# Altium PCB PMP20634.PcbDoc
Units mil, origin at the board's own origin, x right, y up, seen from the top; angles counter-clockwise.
Board outline 3525 x 1240 mil, 2 copper layers (Top Layer, Bottom Layer), stack 62 mil thick; 30 components, 22 nets, 73 pads, 19 vias.
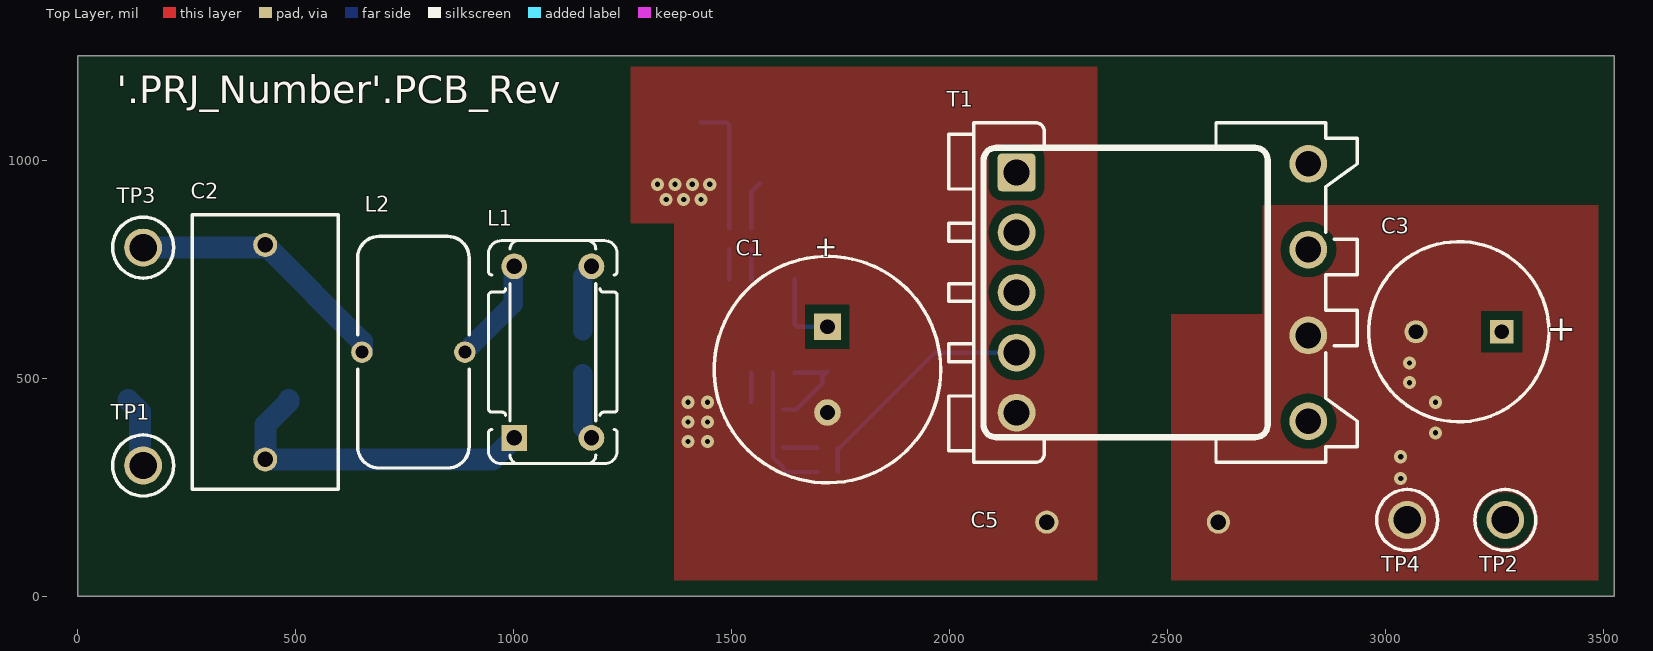
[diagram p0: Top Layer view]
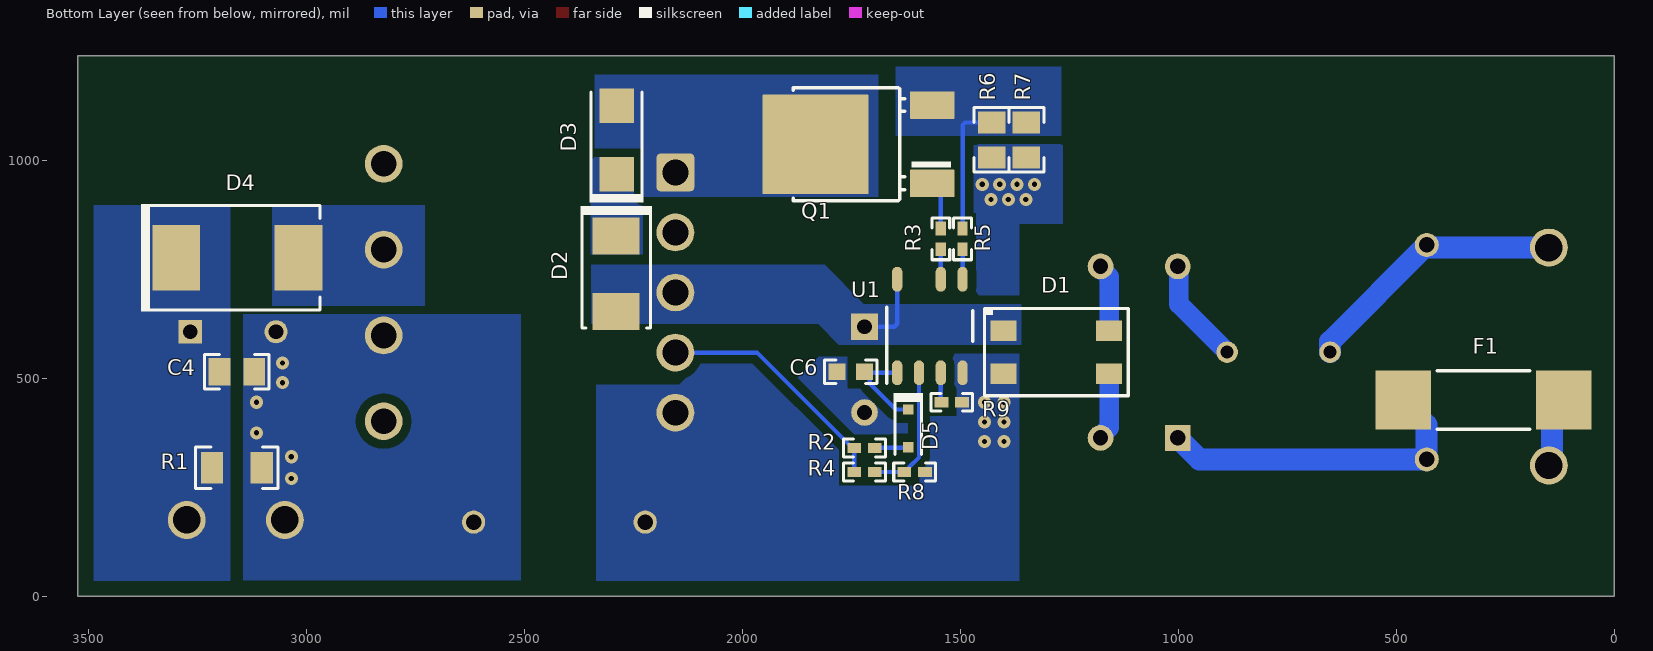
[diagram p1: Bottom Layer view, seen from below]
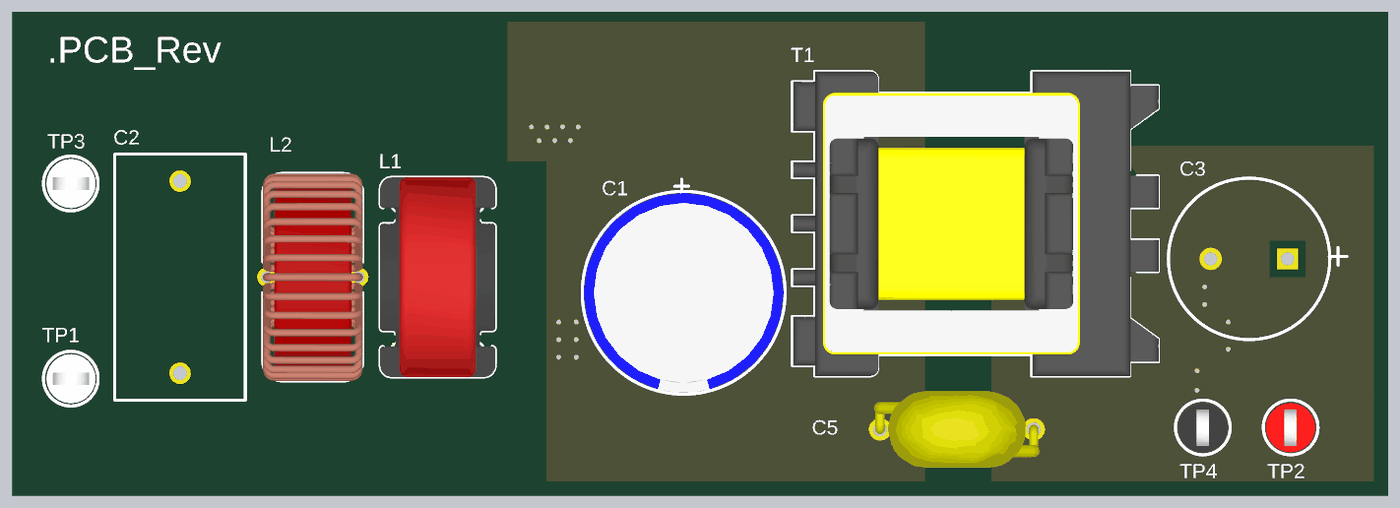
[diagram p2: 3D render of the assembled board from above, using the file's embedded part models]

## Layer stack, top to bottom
Top Solder: solder mask 0.4, Solder Resist, Dk 3.5
Top Layer: signal copper 1.4
Dielectric1: core 59.2, FR-4, Dk 4.8
Bottom Layer: signal copper 1.4
Bottom Solder: solder mask 0.4, Solder Resist, Dk 3.5

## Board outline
0,0 0,1240 3525,1240 3525,0

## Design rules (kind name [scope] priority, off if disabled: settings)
AcuteAngle [All] p1: minimum=4.50000000000000E+0001 checktracksonly=FALSE
AssemblyTestPointUsage [All] p1: valid=2
BoardOutlineClearance BoardOutlineClearance_MountingHoles [OnCopper and InComponentClass('Mounting Holes')] p1: gap=25 ignorepadtopadclearanceinfootprint=FALSE
BoardOutlineClearance BoardOutlineClearance_Poly [OnCopper and InPoly] p2: gap=25 ignorepadtopadclearanceinfootprint=FALSE
BoardOutlineClearance [OnCopper and Not InComponentClass('Logo') and not InComponentClass('FiducialMark') and not InRegion(1000,500,4000,800)] p3: gap=25 ignorepadtopadclearanceinfootprint=FALSE
Clearance Clearance_2 [InNetClass('HV') vs Not InNetClass('HV')] p1: gap=60 ignorepadtopadclearanceinfootprint=FALSE
Clearance Clearance_1 [InNetClass('MV') vs Not InNetClass('MV')] p2: gap=30 ignorepadtopadclearanceinfootprint=FALSE
Clearance Clearance_Keepouts [((IsTrack Or IsArc) And Not InPoly) And IsFree and IsKeepOut vs ((IsTrack Or IsArc) And Not InPoly) And IsFree and IsKeepOut] p3: gap=0 ignorepadtopadclearanceinfootprint=FALSE
Clearance Clearance_BoardEdge_MountingHoles [OnCopper and InComponentClass('Mounting Holes') vs IsKeepOut] p4: gap=40 ignorepadtopadclearanceinfootprint=FALSE except(0: Arc-Hole Track-Hole SMDPad-Hole THPad-Hole Via-Hole Fill-Hole Poly-Hole Region-Hole Text-Hole)
Clearance Clearance_BoardEdge_Poly [OnCopper and InPoly vs IsKeepOut] p5: gap=50 ignorepadtopadclearanceinfootprint=FALSE except(0: Arc-Hole Track-Hole SMDPad-Hole THPad-Hole Via-Hole Fill-Hole Poly-Hole Region-Hole Text-Hole)
Clearance Clearance_BoardEdge [OnCopper and Not InComponentClass('Logo') and not InComponentClass('FiducialMark') and not InRegion(1000,500,4000,800) and Not IsKeepout vs IsKeepOut] p6: gap=50 ignorepadtopadclearanceinfootprint=FALSE
Clearance Clearance_Poly [InPolygon] p7: gap=20 ignorepadtopadclearanceinfootprint=FALSE except(0: Arc-Hole Track-Hole SMDPad-Hole THPad-Hole Via-Hole Fill-Hole Poly-Hole Region-Hole Text-Hole)
Clearance [All] p8: gap=7.87 ignorepadtopadclearanceinfootprint=FALSE except(0: Arc-Hole Track-Hole SMDPad-Hole THPad-Hole Via-Hole Fill-Hole Poly-Hole Region-Hole Text-Hole)
ComponentClearance ComponentClearance_MountingHoles_FiducialMarks [InComponentClass('Mounting Holes') vs InComponentClass('FiducialMark')] p1: gap=20 collisioncheckmode=3 verticalgap=10 showdistances=FALSE
ComponentClearance ComponentClearance_Shunt [InComponentClass('Header') vs InComponentClass('Shunt')] p2: gap=0 collisioncheckmode=3 verticalgap=0 showdistances=FALSE
ComponentClearance ComponentClearance_Logo [InComponentClass('Logo')] p3: gap=5 collisioncheckmode=3 verticalgap=10 showdistances=FALSE
ComponentClearance ComponentClearance_ScrewToNut [(HasFootprint('NY PMS 440 0025 PH')) vs (HasFootprint('Keystone_1902C'))] p4: gap=20 collisioncheckmode=3 verticalgap=100000 showdistances=FALSE
ComponentClearance ComponentClearance_MountingHoles [InComponentClass('Mounting Holes')] p5: gap=20 collisioncheckmode=3 verticalgap=10 showdistances=FALSE
ComponentClearance ComponentClearance_SmallPassives [HasFootprint('0201*') or HasFootprint('0402*') or HasFootprint('0508') or HasFootprint('0603*') or HasFootprint('0612') or HasFootprint('0805*') or HasFootprint('0815*') or HasFootprint('0830*') or HasFootprint('1206*') or HasFootprint('1210*') or HasFootprint('1808*') or HasFootprint('1812*') or HasFootprint('1825*') or HasFootprint('2010*') or HasFootprint('2220*') or HasFootprint('2225*') or HasFootprint('2512*') or HasFootprint('2728*') or HasFootprint('3518*') vs HasFootprint('0201*') or HasFootprint('0402*') or HasFootprint('0508') or HasFootprint('0603*') or HasFootprint('0612') or HasFootprint('0805*') or HasFootprint('0815*') or HasFootprint('0830*') or HasFootprint('1206*') or HasFootprint('1210*') or HasFootprint('1808*') or HasFootprint('1812*') or HasFootprint('1825*') or HasFootprint('2010*') or HasFootprint('2220*') or HasFootprint('2225*') or HasFootprint('2512*') or HasFootprint('2728*') or HasFootprint('3518*')] p6: gap=20 collisioncheckmode=3 verticalgap=20 showdistances=FALSE
ComponentClearance ComponentClearance_THtoSMT [IsThruComponent vs IsSMTComponent] p7: gap=10 collisioncheckmode=3 verticalgap=10 showdistances=FALSE
ComponentClearance ComponentClearance_THtoTH [IsThruComponent vs IsThruComponent] p8: gap=10 collisioncheckmode=3 verticalgap=10 showdistances=FALSE
ComponentClearance [All] p9: gap=10 collisioncheckmode=3 verticalgap=10 showdistances=FALSE
DiffPairsRouting [All] p1: maxlimit=100 minlimit=10 mostfreqgap=10 toplayer_minwidth=15 toplayer_maxwidth=15 toplayer_prefwidth=15 bottomlayer_minwidth=15 bottomlayer_maxwidth=15 bottomlayer_prefwidth=15 maxuncoupledlength=1000
FabricationTestPointUsage TestPointUsage [All] p1: valid=2 allowmultiple=FALSE
FabricationTestpoint Testpoint [All] p1: side=3 testpointundercomponent=TRUE minsize=40 maxsize=100 preferedsize=60 minholesize=0 maxholesize=40 preferedholesize=32 testpointgrid=1 allowsidetop=TRUE allowsidebottom=TRUE usegrid=TRUE gridtolerance=0.01
FanoutControl Fanout_LCC [IsLCC] p1: bgadir=Out bgaviamode=Centered fanoutstyle=Auto fanoutdirection=Alternating viagrid=1 // Fanout_LCC (Default Rule)
FanoutControl Fanout_BGA [IsBGA] p2: bgadir=Out bgaviamode=Centered fanoutstyle=Auto fanoutdirection=Alternating viagrid=1 // Fanout_BGA (Default Rule)
FanoutControl Fanout_Default [All] p4: bgadir=Out bgaviamode=Centered fanoutstyle=Auto fanoutdirection=Alternating viagrid=1 // Fanout_Default (Default Rule)
FanoutControl Fanout_Small [(CompPinCount < 5)] p5: bgadir=Out bgaviamode=Centered fanoutstyle=Auto fanoutdirection=OutThenIn viagrid=1 // Fanout_Small (Default Rule)
Height [All] p1: minheight=0 maxheight=3000 prefheight=500
HoleSize [All] p1: absolutevalues=TRUE maxlimit=251 minlimit=7.87 maxpercent=80.000 minpercent=20.000
MinimumAnnularRing MinimumAnnularRing_ThermalPadVias [IsVia and InAnyComponent] p1: minimumring=5.91
MinimumAnnularRing [All] p2: minimumring=8
MinimumSolderMaskSliver MinimumSolderMaskSliver_Logo [InComponentClass('Logo') vs InComponentClass('Logo')] p1: minsoldermaskwidth=0.7
MinimumSolderMaskSliver [All] p2: minsoldermaskwidth=3.94
PlaneConnect [All] p1: planeconnectstyle=Direct reliefexpansion=10 reliefentries=4 reliefconductorwidth=10 reliefairgap=10
PolygonConnect PolygonConnect_15 [All vs IsNamedPolygon('C109_2') Or  IsNamedPolygon('C107_2') Or  IsNamedPolygon('HV') Or  IsNamedPolygon('Q203_5') Or  IsNamedPolygon('C107_2') Or  IsNamedPolygon('HS') Or  IsNamedPolygon('Q201_5') Or  IsNamedPolygon('Q203_5') Or  IsNamedPolygon('C106_2') Or  IsNamedPolygon('C108_2') Or  IsNamedPolygon('Vout') Or  IsNamedPolygon('Q203_5') Or  IsNamedPolygon('C108_2') Or  IsNamedPolygon('C113_2') Or  IsNamedPolygon('Q203_5') Or  IsNamedPolygon('Q201_5') Or  IsNamedPolygon('C107_2') Or  IsNamedPolygon('C102_1') Or  IsNamedPolygon('SGND') Or  IsNamedPolygon('GND') Or  IsNamedPolygon('SGND') Or  IsNamedPolygon('GND') Or  IsNamedPolygon('IN+') Or  IsNamedPolygon('IN+') Or  IsNamedPolygon('Q201_5') Or  IsNamedPolygon('Q201_5') Or  IsNamedPolygon('SGND') Or  IsNamedPolygon('SGND') Or  IsNamedPolygon('Vout') Or  IsNamedPolygon('Vout') Or  IsNamedPolygon('IN+') Or  IsNamedPolygon('GND') Or  IsNamedPolygon('IN+') Or  IsNamedPolygon('GND')] p1: connectstyle=Direct reliefconductorwidth=10 reliefentries=4 polygonreliefangle="90 Angle" airgapwidth=10
PolygonConnect PolygonConnect_14 [All vs IsNamedPolygon('C106_2') Or  IsNamedPolygon('C107_2') Or  IsNamedPolygon('C107_2') Or  IsNamedPolygon('C107_2') Or  IsNamedPolygon('C102_1') Or  IsNamedPolygon('Q203_5') Or  IsNamedPolygon('Vout') Or  IsNamedPolygon('Q203_5') Or  IsNamedPolygon('Q203_5') Or  IsNamedPolygon('Q201_5') Or  IsNamedPolygon('C108_2') Or  IsNamedPolygon('Q203_5') Or  IsNamedPolygon('HS') Or  IsNamedPolygon('HV') Or  IsNamedPolygon('C108_2') Or  IsNamedPolygon('Q201_5') Or  IsNamedPolygon('C109_2') Or  IsNamedPolygon('Q201_5') Or  IsNamedPolygon('Q201_5') Or  IsNamedPolygon('C113_2')] p2: connectstyle=Direct reliefconductorwidth=10 reliefentries=4 polygonreliefangle="90 Angle" airgapwidth=10
PolygonConnect PolygonConnect_13 [All vs IsNamedPolygon('C102_1') Or  IsNamedPolygon('HV') Or  IsNamedPolygon('C107_2') Or  IsNamedPolygon('C109_2') Or  IsNamedPolygon('C107_2') Or  IsNamedPolygon('C108_2') Or  IsNamedPolygon('C106_2') Or  IsNamedPolygon('C108_2') Or  IsNamedPolygon('C113_2') Or  IsNamedPolygon('C107_2')] p3: connectstyle=Direct reliefconductorwidth=10 reliefentries=4 polygonreliefangle="90 Angle" airgapwidth=10
PolygonConnect PolygonConnect_12 [All vs IsNamedPolygon('C107_2') Or  IsNamedPolygon('C113_2') Or  IsNamedPolygon('C106_2') Or  IsNamedPolygon('C107_2') Or  IsNamedPolygon('C107_2') Or  IsNamedPolygon('C102_1')] p4: connectstyle=Direct reliefconductorwidth=10 reliefentries=4 polygonreliefangle="90 Angle" airgapwidth=10
PolygonConnect PolygonConnect_11 [All vs IsNamedPolygon('C106_2') Or  IsNamedPolygon('C102_1') Or  IsNamedPolygon('C107_2') Or  IsNamedPolygon('C107_2') Or  IsNamedPolygon('C107_2')] p5: connectstyle=Direct reliefconductorwidth=10 reliefentries=4 polygonreliefangle="90 Angle" airgapwidth=10
PolygonConnect PolygonConnect_10 [All vs IsNamedPolygon('C106_2')] p6: connectstyle=Direct reliefconductorwidth=10 reliefentries=4 polygonreliefangle="90 Angle" airgapwidth=10
PolygonConnect PolygonConnect_9 [All vs IsNamedPolygon('C11_1') Or  IsNamedPolygon('Vin') Or  IsNamedPolygon('Vin') Or  IsNamedPolygon('5V') Or  IsNamedPolygon('D6_2') Or  IsNamedPolygon('Q3_3') Or  IsNamedPolygon('GND2') Or  IsNamedPolygon('GND2') Or  IsNamedPolygon('GND') Or  IsNamedPolygon('Q3_4') Or  IsNamedPolygon('12V5') Or  IsNamedPolygon('GND') Or  IsNamedPolygon('12V5') Or  IsNamedPolygon('D3_1')] p7: connectstyle=Direct reliefconductorwidth=10 reliefentries=4 polygonreliefangle="90 Angle" airgapwidth=10
PolygonConnect PolygonConnect_8 [All vs IsNamedPolygon('C11_1') Or  IsNamedPolygon('Vin') Or  IsNamedPolygon('12V5') Or  IsNamedPolygon('Q3_3') Or  IsNamedPolygon('GND2') Or  IsNamedPolygon('GND2') Or  IsNamedPolygon('5V') Or  IsNamedPolygon('Q3_4') Or  IsNamedPolygon('12V5')] p8: connectstyle=Direct reliefconductorwidth=10 reliefentries=4 polygonreliefangle="90 Angle" airgapwidth=10
PolygonConnect PolygonConnect_7 [All vs IsNamedPolygon('GND2') Or  IsNamedPolygon('GND2') Or  IsNamedPolygon('5V') Or  IsNamedPolygon('12V5') Or  IsNamedPolygon('12V5') Or  IsNamedPolygon('C11_1')] p9: connectstyle=Direct reliefconductorwidth=10 reliefentries=4 polygonreliefangle="90 Angle" airgapwidth=10
PolygonConnect PolygonConnect_6 [All vs IsNamedPolygon('GND2') Or  IsNamedPolygon('SGND') Or  IsNamedPolygon('GND1') Or  IsNamedPolygon('C901_1') Or  IsNamedPolygon('SGND') Or  IsNamedPolygon('GND2') Or  IsNamedPolygon('GND1')] p10: connectstyle=Direct reliefconductorwidth=10 reliefentries=4 polygonreliefangle="90 Angle" airgapwidth=10
PolygonConnect PolygonConnect_5 [All vs IsNamedPolygon('GND1') Or  IsNamedPolygon('GND1')] p11: connectstyle=Direct reliefconductorwidth=10 reliefentries=4 polygonreliefangle="90 Angle" airgapwidth=10
PolygonConnect PolygonConnect_4 [All vs IsNamedPolygon('C21_1') Or  IsNamedPolygon('C5_1') Or  IsNamedPolygon('C12_2') Or  IsNamedPolygon('C2_2') Or  IsNamedPolygon('C13_1') Or  IsNamedPolygon('C28_1') Or  IsNamedPolygon('C6_1') Or  IsNamedPolygon('GND') Or  IsNamedPolygon('GND2') Or  IsNamedPolygon('C14_1') Or  IsNamedPolygon('C13_1') Or  IsNamedPolygon('Q1_3') Or  IsNamedPolygon('C14_1') Or  IsNamedPolygon('C5_1') Or  IsNamedPolygon('GND2') Or  IsNamedPolygon('C28_1') Or  IsNamedPolygon('D5_2') Or  IsNamedPolygon('D6_2') Or  IsNamedPolygon('D2_1') Or  IsNamedPolygon('C12_2') Or  IsNamedPolygon('D2_1') Or  IsNamedPolygon('C4_1') Or  IsNamedPolygon('C4_1') Or  IsNamedPolygon('C2_2') Or  IsNamedPolygon('GND') Or  IsNamedPolygon('C33_1') Or  IsNamedPolygon('C9_1')] p12: connectstyle=Direct reliefconductorwidth=10 reliefentries=4 polygonreliefangle="90 Angle" airgapwidth=10
PolygonConnect PolygonConnect_3 [All vs IsNamedPolygon('C28_1') Or  IsNamedPolygon('C12_2') Or  IsNamedPolygon('C28_1') Or  IsNamedPolygon('C9_1') Or  IsNamedPolygon('D5_2') Or  IsNamedPolygon('C12_2') Or  IsNamedPolygon('C2_2') Or  IsNamedPolygon('C14_1') Or  IsNamedPolygon('C4_1') Or  IsNamedPolygon('C14_1') Or  IsNamedPolygon('D6_2') Or  IsNamedPolygon('GND2') Or  IsNamedPolygon('Q1_3') Or  IsNamedPolygon('C5_1') Or  IsNamedPolygon('D2_1') Or  IsNamedPolygon('C4_1') Or  IsNamedPolygon('C13_1') Or  IsNamedPolygon('C5_1') Or  IsNamedPolygon('C13_1') Or  IsNamedPolygon('C33_1') Or  IsNamedPolygon('D2_1') Or  IsNamedPolygon('GND') Or  IsNamedPolygon('GND') Or  IsNamedPolygon('GND2') Or  IsNamedPolygon('C2_2') Or  IsNamedPolygon('C6_1') Or  IsNamedPolygon('C21_1')] p13: connectstyle=Direct reliefconductorwidth=10 reliefentries=4 polygonreliefangle="90 Angle" airgapwidth=10
PolygonConnect PolygonConnect_2 [All vs IsNamedPolygon('C21_1') Or  IsNamedPolygon('C4_1') Or  IsNamedPolygon('D5_2') Or  IsNamedPolygon('C5_1') Or  IsNamedPolygon('C14_1') Or  IsNamedPolygon('C13_1') Or  IsNamedPolygon('C4_1') Or  IsNamedPolygon('C33_1') Or  IsNamedPolygon('C12_2') Or  IsNamedPolygon('D2_1') Or  IsNamedPolygon('C2_2') Or  IsNamedPolygon('C28_1') Or  IsNamedPolygon('C12_2') Or  IsNamedPolygon('D2_1') Or  IsNamedPolygon('C5_1') Or  IsNamedPolygon('Q1_3') Or  IsNamedPolygon('GND') Or  IsNamedPolygon('D6_2') Or  IsNamedPolygon('C6_1') Or  IsNamedPolygon('C2_2') Or  IsNamedPolygon('C14_1') Or  IsNamedPolygon('C28_1') Or  IsNamedPolygon('C13_1') Or  IsNamedPolygon('C9_1') Or  IsNamedPolygon('GND')] p14: connectstyle=Direct reliefconductorwidth=10 reliefentries=4 polygonreliefangle="90 Angle" airgapwidth=10
PolygonConnect PolygonConnect_1 [All vs IsNamedPolygon('C28_1') Or  IsNamedPolygon('D5_2') Or  IsNamedPolygon('C5_1') Or  IsNamedPolygon('C5_1') Or  IsNamedPolygon('D2_1') Or  IsNamedPolygon('C21_1') Or  IsNamedPolygon('C9_1') Or  IsNamedPolygon('C4_1') Or  IsNamedPolygon('C14_1') Or  IsNamedPolygon('C28_1') Or  IsNamedPolygon('C6_1') Or  IsNamedPolygon('C12_2') Or  IsNamedPolygon('C33_1') Or  IsNamedPolygon('C4_1') Or  IsNamedPolygon('C13_1') Or  IsNamedPolygon('C12_2') Or  IsNamedPolygon('D6_2') Or  IsNamedPolygon('C2_2') Or  IsNamedPolygon('C14_1') Or  IsNamedPolygon('D2_1') Or  IsNamedPolygon('C2_2') Or  IsNamedPolygon('C13_1')] p15: connectstyle=Direct reliefconductorwidth=10 reliefentries=4 polygonreliefangle="90 Angle" airgapwidth=10
PolygonConnect [All] p16: connectstyle=Direct reliefconductorwidth=10 reliefentries=4 polygonreliefangle="90 Angle" airgapwidth=10
RoutingVias ThermalPadVias [IsVia and InAnyComponent] p1: holewidth=7.87 width=19.68 viastyle="Through Hole" minholewidth=7.87 minwidth=19.68 maxholewidth=12.99 maxwidth=23.62
RoutingVias [All] p2: holewidth=16 width=34 viastyle="Through Hole" minholewidth=7.87 minwidth=20 maxholewidth=40 maxwidth=65
SilkToBoardRegionClearance [Not ((IsComment or IsDesignator) And (Hide <> 'False')) and not InRegion(1000,500,4000,800)] p1:
SilkToSilkClearance SilkToSilkClearance_Pb-FreeLogo [(HasFootprint('Pb-Free_Overlay_Medium') OR HasFootprint('Pb-Free_Overlay_Small')) vs (HasFootprint('Pb-Free_Overlay_Medium') OR HasFootprint('Pb-Free_Overlay_Small'))] p1: silktosilkclearance=0
SilkToSilkClearance [All] p2: silktosilkclearance=4
SilkToSolderMaskClearance SilkToComponentPadClearance [IsPad and InAnycomponent] p1: minsilkscreentomaskgap=5 clearancetoexposedcopper=TRUE
SilkToSolderMaskClearance "Silk to Solder Mask Opening" [All] p2: minsilkscreentomaskgap=4 clearancetoexposedcopper=FALSE
SolderMaskExpansion [All] p1: expansion=1.97 istentingtop=FALSE
Width [All] p1: maxlimit=100 minlimit=6 preferedwidth=10 checkconnectedcopper=TRUE
14 further rules are at their usual default settings.

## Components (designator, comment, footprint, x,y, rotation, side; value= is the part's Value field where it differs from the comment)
C1 "EKXG401ELL220MK20S" KXG_1250x2000 1720,520 r270 top value=22uF
C2 "ECQ-U3A104MG" ECQUG_1500x800x1500 430,560 r90 top value=0.1uF
C3 "EKZE250ELL681MJ20S" Chemi-Con_1000x2000 3168.58,606.85 r180 top value=680uF
C4 "GRM219R61E106KA12" 0805_HV 3160,515 r180 bottom value=10uF
C5 "VY1102M35Y5UQ63V0" VY1_900x500x1300 2420,170 r180 top value=1000pF
C6 "GRM188R6YA475KE15D" 0603 1751.5,515 r0 bottom value=4.7uF
D1 "RH06-T" MiniDIP 1280,560 r180 bottom value=600V
D2 "SMBJ150A-13-F" SMB 2290,740 r270 bottom value=150V
D3 "MURA160T3G" SMA 2288.58,1046.85 r90 bottom value=1.05V
D4 "B3100-13-F" SMC 3158.58,776.85 r180 bottom value=100V
D5 "BAS16J,135" SOD-323F 1620,385 r270 bottom value=100V
F1 "0443001.DR" FUSE_0443 300,450 r180 bottom
L1 "744821150" WE-CMB_XS 1090,560 r90 top value=5mH
L2 "7447031" WE-FI_1350x700 770,560 r0 top value=140uH
Q1 "FCD4N60TM" DPAK 1698.58,1036.85 r0 bottom value=600V
R1 "CRCW120610K0JNEA" 1206 3160,295 r0 bottom value=10k
R2 "CRCW04020000Z0ED" 0402 1720,340 r0 bottom value=0
R3 "CRCW04020000Z0ED" 0402 1545,820 r90 bottom value=0
R4 "CRCW040273K2FKED" 0402 1720,285 r0 bottom value=73.2k
R5 "CRCW04021K33FKED" 0402 1495,820 r90 bottom value=1.33k
R6 "CRCW08051R60JNEA" 0805_HV 1428.58,1046.85 r90 bottom value=1.6
R7 "CRCW08051R60JNEA" 0805_HV 1348.58,1046.85 r90 bottom value=1.6
R8 "CRCW040233K2FKED" 0402 1605,285 r0 bottom value=33.2k
R9 "CRCW0402115KFKED" 0402 1520,445 r0 bottom value=115k
T1 "750316686" Wurth_EE16-8-5_5280 2488.58,696.85 r0 top value=500uH
TP1 "5012" Keystone5012 150,300 r90 top
TP2 "5010" Keystone5010 3275,175 r0 top
TP3 "5012" Keystone5012 150,800 r90 top
TP4 "5011" Keystone5011 3050,175 r0 top
U1 "UCC28730DR" D0007A_N 1570,620 r90 bottom

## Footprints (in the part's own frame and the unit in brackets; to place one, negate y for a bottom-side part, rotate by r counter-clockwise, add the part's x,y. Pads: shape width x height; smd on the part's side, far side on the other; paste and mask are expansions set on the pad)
0402 [mm] "0402 from SM-752 data"
  rect 0.8x0.6 smd: 1(-0.6,0) 2(0.6,0)
  silkscreen extent -1.22,-0.52 1.22,0.52, body extent -0.55,-0.3 0.55,0.3, height 0.6
0603 [mm] "0603 from SM-752 data"
  rect 1x0.95 smd: 1(-0.8,0) 2(0.8,0)
  silkscreen extent -1.52,-0.69 1.52,0.69, body extent -0.87,-0.47 0.87,0.47, height 1
0805_HV [mil] "0805 with 30mil clearance between pads"
  rect 50x63 smd: 1(-40,0) 2(40,0)
  silkscreen extent -74,-40 74,40, body extent -43,-29 43,29, height 57
1206 [mm] "1206 from SM-752 data"
  rect 1.3x1.85 smd: 1(-1.45,0) 2(1.45,0)
  silkscreen extent -2.4,-1.21 2.4,1.21, body extent -1.7,-0.9 1.7,0.9, height 1.35
Chemi-Con_1000x2000 [mm] "TH, 2-Leads, Body 10x20mm, Pin Spacing 5mm"
  rect 1.35x1.35 hole 0.85: 1(-2.5,0)
  round 1.35 hole 0.85: 2(2.5,0)
  silkscreen extent -5.25,-5.25 5.25,5.25, body extent -5.25,-5.25 5.25,5.25, height 21.5
D0007A_N [mm] "SOIC, 7-Leads, Body 4.9x3.9mm, Pitch 1.27mm, IPC Medium Density"
  oval 1.45x0.6 smd: 1(-2.725,1.905) 2(-2.725,0.635) 3(-2.725,-0.635) 4(-2.725,-1.905) 5(2.725,-1.905) 6(2.725,-0.635) 8(2.725,1.905)
  silkscreen extent -3.32,-2.5 1.1,2.52, body extent -3.01,-2.45 3.01,2.45, height 1.75
DPAK [mm] "D-PAK, 3-Pads, Body 6.22x6.73mm (max), TO-252AA using nominal STEP model"
  rrect6% 2.6x1.6 smd: 1(-3.4,2.28) 3(-3.4,-2.28)
  rrect2% 6.2x5.8 smd paste-2.9: 4(3.4,0)
  silkscreen extent -4.5,-3.3 4.7,3.28, body extent -3.86,-3.29 5.84,3.29, height 2.48
ECQUG_1500x800x1500 [mm] "TH, 2-Leads, Body 15x8mm, Pin Spacing 12.5mm"
  round 1.4 hole 0.9: 1(-6.25,0) 2(6.25,0)
  silkscreen extent -8,-4.25 8,4.25, body extent -8,-4.25 8,4.25, height 15.5
FUSE_0443 [mm] "LITTELFUSE"
  rect 3.25x3.43 smd: 1(-4.675,0) 2(4.675,0)
  silkscreen extent -2.7,-1.7 2.7,1.7, body extent -5.05,-1.56 5.05,1.56, height 3.12
Keystone5010 [mil] "Keystone Multipurpose loops"
  round 87 hole 63: 1(0,0)
  silkscreen extent -70,-70 70,70, body extent -63,-63 63,62, height 319
Keystone5011 [mil] "Keystone Multipurpose loops"
  round 87 hole 63: 1(0,0)
  silkscreen extent -70,-70 70,70, body extent -63,-63 63,62, height 319
Keystone5012 [mil] "Keystone Multipurpose loops"
  round 87 hole 63: 1(0,0)
  silkscreen extent -70,-70 70,70, body extent -63,-63 63,62, height 319
KXG_1250x2000 [mm] "United Chemicon"
  rect 1.55x1.55 hole 0.85: 1(-2.5,0)
  round 1.55 hole 0.85: 2(2.5,0)
  silkscreen extent -6.6,-6.6 6.6,6.6, body extent -6.45,-6.49 6.49,6.49, height 21.51
MiniDIP [mm] "Land pattern created based on STEP model."
  rect 1.52x1.2 smd: 1(-3.075,1.25) 2(-3.075,-1.25) 3(3.075,-1.25) 4(3.075,1.25)
  silkscreen extent -4.19,-2.54 4.19,2.54, body extent -3.5,-2.45 3.5,2.45, height 2.75
SMA [mm] "Molded Diode, 2-Leads, Body 4.3x2.6mm, IPC Medium Density, based on OnSemi component dimensions and land pattern"
  rect 2x2 smd: 1(-2,0) 2(2,0)
  silkscreen extent -3.66,-1.57 2.79,1.57, body extent -2.6,-1.3 2.6,1.3, height 2.42
SMB [mil] "Molded Diode, 2-Leads, Body 5.4x3.6mm, IPC Medium Density, based on OnSemi component dimensions"
  rect 85x107.99 smd: 1(-87.01,0) 2(87.01,0)
  silkscreen extent -155,-82 125,82, body extent -106,-71 106,71, height 91
SMC [mil] "Molded Diode, 2-Leads, Body 6.9x5.8mm, IPC Medium Density, based on OnSemi component dimensions and land patterns"
  rect 110x150 smd: 1(-140.49,0) 2(140.49,0)
  silkscreen extent -221,-123 189,124, body extent -156,-116 157,116, height 91
SOD-323F [mm] "NXP recommended land pattern"
  rect 0.6x0.6 smd paste-0.05: 1(-1.1,0) 2(1.1,0)
  silkscreen extent -2.06,-0.86 1.53,0.86, body extent -1.35,-0.68 1.35,0.67, height 0.79
VY1_900x500x1300 [mm] "TH, Body 9x5mm, PinSpacing 10mm"
  round 1.35 hole 0.9: 1(-5,0) 2(5,0)
  body extent -5.4,-2.5 5.4,2.5, height 12.93
WE-CMB_XS [mm] "WE-CMB Series Size XS"
  rect 1.5x1.5 hole 0.9: 1(-5,2.25)
  round 1.5 hole 0.9: 2(-5,-2.25) 3(5,-2.25) 4(5,2.25)
  silkscreen extent -6.5,-3.75 6.5,3.75, body extent -6.5,-3.75 6.5,3.75, height 16.24
WE-FI_1350x700 [mm] "TH, 2-Leads, Dia 13.5mm"
  round 1.25 hole 0.75: 1(-3,0) 2(3,0)
  silkscreen extent -3.25,-6.75 3.25,6.75, body extent -3.25,-6.75 3.25,6.75, height 13.32
Wurth_EE16-8-5_5280 [mm] "Wurth"
  rrect20% 2.2x2.2 hole 1.5: 1(-8.5,7)
  round 2.2 hole 1.5: 2(-8.5,3.5) 3(-8.5,0) 4(-8.5,-3.5) 5(-8.5,-7) 6(8.5,-7.5) 7(8.5,-2.5) 8(8.5,2.5) 9(8.5,7.5)
  silkscreen extent -12.45,-9.9 11.36,9.9, body extent -12.4,-9.9 11.41,9.9, height 14.9

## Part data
C1: "CAP, AL, 22 µF, 400 V, +/- 20%, TH", Cap_Case=12.5x20, Manufacturer=Chemi-Con, Supplier Part Number 1=565-1463-ND, Tolerance_%=20, Value1=Unknown, Value2=400V, ValueDisplayed=22µF
C2: library part CMP-0012502-3, "CAP, Film, 0.1 uF, 300 V, +/- 20%, TH", Cap_Case=15x8x15mm, Manufacturer=Panasonic, Supplier Part Number 1=P11116-ND, Tolerance_%=20%, Value1=Unknown, Value2=300V, ValueDisplayed=0.1uF
C3: "CAP, AL, 680 µF, 25 V, +/- 20%, TH", Cap_Case=10x20, Manufacturer=Chemi-Con, Supplier Part Number 1=565-1679-ND, Tolerance_%=20, Value1=Unknown, Value2=25V, ValueDisplayed=680µF
C4: "CAP, CERM, 10 µF, 25 V, +/- 10%, X5R, 0805", Cap_Case=0805, Manufacturer=MuRata, Supplier Part Number 1=490-7207-1-ND, TempCo=X5R, Tolerance_%=10, Value1=Unknown, Value2=25V, ValueDisplayed=10µF
C5: library part CMP-0086097-1, "CAP, CERM, 1000 pF, X1 760 VAC/Y1 500 VAC, +/- 20%, Y5U, 9x5mm", Cap_Case=9X5mm, Manufacturer=Vishay-Bccomponents, TempCo=Y5U, Tolerance_%=20%, ValueDisplayed=1000pF
C6: "CAP, CERM, 4.7 µF, 35 V, +/- 10%, X5R, 0603", Cap_Case=0603, Manufacturer=MuRata, Supplier Part Number 1=490-7205-1-ND, TempCo=X5R, Tolerance_%=10, Value1=Unknown, Value2=35V, ValueDisplayed=4.7µF
D1: "Diode, Switching-Bridge, 600 V, 0.5 A, MiniDIP", Manufacturer="Diodes Inc.", Supplier Part Number 1=RH06DICT-ND, Value1=0.5A, Value2=1.15V
D2: "Diode, TVS, Uni, 150 V, 243 Vc, SMB", Manufacturer="Diodes Inc.", Power_W=5, Supplier Part Number 1=SMBJ150A-FDICT-ND, Value1=5W
D3: "Diode, Ultrafast, 600V, 1A, SMA", Manufacturer="ON Semiconductor", Supplier Part Number 1=MURA160T3GOSCT-ND, Value1=1A, Value2=600V
D4: "Diode, Schottky, 100 V, 3 A, SMC", Manufacturer="Diodes Inc.", Supplier Part Number 1=B3100-FDICT-ND, Value1=3A, Value2=0.79V
D5: "Diode, Switching, 100 V, 0.25 A, SOD-323F", Manufacturer="NXP Semiconductor", Supplier Part Number 1=568-5996-1-ND, Value1=0.25A, Value2=V
F1: "Fuse, 1 A, 250VAC/VDC, SMD", Irating_A=1, Manufacturer=Littelfuse, Supplier Part Number 1=F2906CT-ND
L1: library part CMP-0084275-1, "Coupled inductor, 5 mH, 0.22 ohm, TH", Manufacturer="Wurth Elektronik", ValueDisplayed=5mH
L2: library part CMP-0064732-2, "Inductor, Toroid, Powdered Iron, 140 uH, 1 A, 0.11 ohm, TH", Manufacturer="Wurth Elektronik", Value1="0.11 ohm", Value2=1A, ValueDisplayed=140uH
Q1: "MOSFET, N-CH, 600 V, 3.9 A, DPAK", Alternate Manufacturer=None, Manufacturer="Fairchild Semiconductor", Supplier Part Number 1=FCD4N60TMCT-ND, Value1="? ohm", Value2="12.8 nC"
R1: library part CMP-0018576-3, "RES, 10 k, 5%, 0.25 W, AEC-Q200 Grade 0, 1206", Manufacturer=Vishay-Dale, Power_W=250mW, Supplier Part Number 1=541-10KECT-ND, TempCo="200 ppm/C", Tolerance_%=5%, Value2=0.25W, Value_Code=10k0, ValueDisplayed=10k
R2 R3: "RES, 0, 5%, 0.063 W, 0402", Manufacturer=Vishay-Dale, Power_W=0.063, Supplier Part Number 1=541-0.0JCT-ND, TempCo="200 ppm/C", Tolerance_%=5, Value1=5%, Value2=0.063W, Value_Code=0000, ValueDisplayed=0
R4: "RES, 73.2 k, 1%, 0.063 W, 0402", Manufacturer=Vishay-Dale, Power_W=0.063, Supplier Part Number 1=541-73.2KLCT-ND, TempCo="100 ppm/C", Tolerance_%=1, Value1=1%, Value2=0.063W, Value_Code=73k2, ValueDisplayed=73.2k
R5: "RES, 1.33 k, 1%, 0.063 W, 0402", Manufacturer=Vishay-Dale, Power_W=0.063, Supplier Part Number 1=541-1.33KLCT-ND, TempCo="100 ppm/C", Tolerance_%=1, Value1=1%, Value2=0.063W, Value_Code=1k33, ValueDisplayed=1.33k
R6 R7: "RES, 1.6, 5%, 0.125 W, 0805", Manufacturer=Vishay-Dale, Power_W=0.125, Supplier Part Number 1=541-1.6ACT-ND, TempCo="200 ppm/C", Tolerance_%=5, Value1=5%, Value2=0.125W, Value_Code=1R60, ValueDisplayed=1.6
R8: "RES, 33.2 k, 1%, 0.063 W, 0402", Manufacturer=Vishay-Dale, Power_W=0.063, Supplier Part Number 1=541-33.2KLCT-ND, TempCo="100 ppm/C", Tolerance_%=1, Value1=1%, Value2=0.063W, Value_Code=33k2, ValueDisplayed=33.2k
R9: "RES, 115 k, 1%, 0.063 W, 0402", Manufacturer=Vishay-Dale, Power_W=0.063, Supplier Part Number 1=541-115KLCT-ND, TempCo="100 ppm/C", Tolerance_%=1, Value1=1%, Value2=0.063W, Value_Code=115k
T1: "Transformer, 500 uH, EE16/8/5, TH", Manufacturer="Wurth Elektronik", ValueDisplayed=500µH
TP1 TP3: "Test Point, Multipurpose, White, TH", Color=White, Manufacturer=Keystone, Supplier Part Number 1=36-5012-ND
TP2: "Test Point, Multipurpose, Red, TH", Color=Red, Manufacturer=Keystone, Supplier Part Number 1=36-5010-ND
TP4: "Test Point, Multipurpose, Black, TH", Color=Black, Manufacturer=Keystone, Supplier Part Number 1=36-5011-ND
U1: "Constant-Voltage Constant-Current Flyback Controller With PSR and Wake-Up Monitoring, D0007A (SOIC-7)", Alternate Manufacturer="Texas Instruments", Alternate PartNumber=UCC28730D

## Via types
v1: diameter 30, hole 12, Top Layer to Bottom Layer, tented top, 13 vias
v2: diameter 30, hole 12, Top Layer to Bottom Layer, tented bottom, 6 vias

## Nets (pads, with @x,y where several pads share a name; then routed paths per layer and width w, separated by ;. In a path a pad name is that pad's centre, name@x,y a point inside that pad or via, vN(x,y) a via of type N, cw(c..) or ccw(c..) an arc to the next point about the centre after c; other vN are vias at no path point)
12VOUT: C3.1 C4.1 D4.1 R1.2 TP2.1
GND: C3.2 C4.2 C5.1 R1.1 T1.7 TP4.1
  other v1: 3035,270 3035,320 3115,375 3115,445 3055,490 3055,535
HV: C1.1 D1.1 D2.2 T1.3 U1.8 | length 180
  Bottom Layer w10: U1.8 1645,625 1651.57,618.43 C1.1
NetC2_1: C2.1 F1.1 L1.1 | length 750.3
  Bottom Layer w50: F1.1 484.06,446.46 430.98,393.38 430.98,314.92 C2.1 952.2,313.94 L1.1
NetC2_2: C2.2 L2.1 TP3.1 | length 620.5
  Bottom Layer w50: TP3.1 422.55,800 428.62,806.06 C2.2 651.89,584.17 L2.1
NetD1_3: D1.3 L1.2 | length 155.8
  Bottom Layer w45: D1.3 1158.94,386.6 1178.58,366.95 L1.2
NetD1_4: D1.4 L1.3 | length 155.8
  Bottom Layer w45: D1.4 1158.94,733.4 1178.58,753.05 L1.3
NetD2_1: D2.1 D3.1
NetD3_2: D3.2 Q1.4 T1.1
NetD4_2: D4.2 T1.8
NetD5_2: D5.2 R2.1 | length 77.1
  Bottom Layer w10: D5.2 1620.85,340.85 1695.53,340.85 R2.1
NetF1_2: F1.2 TP1.1 | length 164.1
  Bottom Layer w50: F1.2 142.92,423.02 142.92,307.08 TP1.1
NetL1_4: L1.4 L2.2 | length 243.8
  Bottom Layer w45: L2.2 998.73,670.62 998.73,754.16 L1.4
NetQ1_1: Q1.1 R3.2 | length 111.6
  Bottom Layer w10: R3.2 1545,927.36 Q1.1
NetQ1_3: Q1.3 R5.2 R6.2 R7.2 | length 306.2
  Bottom Layer w10: R6.2 1489.14,1086.85 1495,1080.99 R5.2
NetR2_2: R2.2 R4.2 T1.4 | length 556.1
  Bottom Layer w10: R4.2 R2.2 1747.56,340 1966.61,559.06 T1.4
NetR3_1: R3.1 U1.6 | length 69.1
  Bottom Layer w10: U1.6 R3.1
NetR4_1: R4.1 R8.2 U1.2 | length 311.7
  Bottom Layer w10: U1.2 1595,318.62 1617.87,295.75 1617.87,291.81 1624.68,285 R4.1
NetR5_1: R5.1 U1.5 | length 69.1
  Bottom Layer w10: U1.5 R5.1
NetR9_2: R9.2 U1.3 | length 68.3
  Bottom Layer w10: R9.2 1545,446.38 U1.3
PGND: C1.2 C5.2 C6.2 D1.2 R6.1 R7.1 R8.1 R9.1 T1.5 U1.4
  other v1: 1350,910 1390,910 1430,910 1330,945 1370,945 1410,945 1450,945
  other v2: 1400,355 1445,355 1400,400 1445,400 1400,445 1445,445
VDD: C6.1 D5.1 U1.1 | length 220.6
  Bottom Layer w10: D5.1 1648.31,428.31 1707.7,487.7 1707.7,502.7 C6.1 1717.72,512.72 U1.1
pads on no net: T1.2 T1.6 T1.9

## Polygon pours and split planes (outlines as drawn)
HV on Bottom Layer "BOTTOM_LAYER_HV_P026" (solid, remove dead copper, pour order 26): 1826.73,625 1778.58,576.85 1658.58,576.85 1360,576.85 1360,670 1721.73,670 1811.73,760 2347.08,760 2347.08,625
PGND on Bottom Layer "BOTTOM_LAYER_PGND_P027" (solid, remove dead copper, pour order 27): 1265,1029.51 1265,855 1365,855 1365,35 2335,35 2335,485 2145,485 1595,1035 1265,1035
GND on Bottom Layer "BOTTOM_LAYER_GND_P018" (solid, remove dead copper, pour order 18): 2508.58,646.85 2508.58,36.85 3145,36.85 3145,646.85
PGND on Bottom Layer "BOTTOM_LAYER_PGND_P016" (solid, remove dead copper, pour order 16): 1268.58,1056.85 1268.58,870 1460,870 1460,1056.85
12VOUT on Bottom Layer "BOTTOM_LAYER_12VOUT_P014" (solid, remove dead copper, pour order 14): 3175,896.85 3175,35 3488.58,35 3488.58,896.85
NetD4_2 on Bottom Layer "BOTTOM_LAYER_NETD4_2_P012" (solid, remove dead copper, pour order 12): 2728.58,896.85 2728.58,666.85 3078.58,666.85 3078.58,896.85 2728.58,896.85
NetD2_1 on Bottom Layer "BOTTOM_LAYER_NETD2_1_P008" (solid, remove dead copper, pour order 8): 2228.58,1046.85 2228.58,785 2348.58,785 2348.58,1046.85
NetD3_2 on Bottom Layer "BOTTOM_LAYER_NETD3_2_P006" (solid, remove dead copper, pour order 6): 1688.58,1196.85 1688.58,916.85 2338.58,916.85 2338.58,1196.85
NetQ1_3 on Bottom Layer "BOTTOM_LAYER_NETQ1_3_P004" (solid, remove dead copper, pour order 4): 1268.58,1216.85 1268.58,1056.85 1648.58,1056.85 1648.58,1216.85
GND on Top Layer "TOP_LAYER_GND_P024" (solid, remove dead copper, pour order 24): 2508.58,36.85 2508.58,646.85 2718.58,646.85 2718.58,896.85 3488.58,896.85 3488.58,216.85 3488.58,36.85 2508.58,36.85
PGND on Top Layer "TOP_LAYER_PGND_P022" (solid, remove dead copper, pour order 22): 2338.58,1216.85 1268.58,1216.85 1268.58,856.85 1269.4,856.04 1368.58,856.04 1368.58,36.85 2338.58,36.85

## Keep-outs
Keep-Out Layer:
  text ".Layer_Name" at 577,-858.49 h60

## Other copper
Top Layer:
  text ".Layer_Name" at 577,-858.49 h60
Bottom Layer:
  pour cut-out: 1755,550 1825,550 1875,500 1890,515 1835,570 1755,570
  text ".Layer_Name" at 577,-858.49 h60

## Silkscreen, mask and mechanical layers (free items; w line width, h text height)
Top Overlay:
  text "'.PRJ_Number'.PCB_Rev" at 90,1110 h108.27
  text ".Layer_Name" at 577,-858.49 h60
Bottom Overlay:
  text ".Layer_Name" at 577,-858.49 h60
Top Paste:
  text ".Layer_Name" at 577,-858.49 h60
Bottom Paste:
  text ".Layer_Name" at 577,-858.49 h60
Top Solder:
  text ".Layer_Name" at 577,-858.49 h60
  text ".Layer_Name" at 577,-858.49 h60
Bottom Solder:
  text ".Layer_Name" at 577,-858.49 h60
Drill Guide:
  text ".Layer_Name" at 577,-858.49 h60
M1 Board Outline:
  the board outline again, w10
  text ".Layer_Name" at 577,-858.49 h60
M2 Board Dimensions:
  rectangle: 0,-275 125,-150
  rectangle: 125,-400 500,-275
  lines w7: 0,-275 1000,-275 ; 125,-400 125,-150 ; 250,-400 250,-150 ; 500,-400 500,-150 ; 750,-400 750,-150 ; 0,-400 1000,-400 1000,-150 0,-150 0,-400
  text ".Layer_Name" at 577,-858.49 h60
M3 3D STEP Top:
  text ".Layer_Name" at 577,-858.49 h60
M4 3D STEP Bottom:
  text ".Layer_Name" at 577,-858.49 h60
M5 Assembly Top:
  lines w10: -292,-930.17 6308,-930.17 ; -292,-726.83 6310,-726.83 ; -292,-523.5 -292,-1133.5 3713,-1133.5 6310,-1133.5 6310,-523.5 -291.5,-523.5 -291.5,-1133.5 1284,-1133.5 ; 2173,-1133.5 2173,-523.5 ; 3440,-726.83 3440,-523.5 ; 4280,-726.83 4280,-523.5 ; 4902,-1140 4902,-937.17
  text "COMPONENTS MARKED 'DNP' SHOULD NOT BE POPULATED." at 1153.5,-318.5 h60
  text "ASSEMBLY VARIANT:" at 1153,-434 h60
  text ".VariantName" at 2189,-434 h60
  text "PCB VIEWED FROM TOP SIDE" at -228.5,-655.67 h60
  text "BOARD #:" at 2248,-655.67 h60
  text ".PRJ_Number" at 2793.5,-655.67 h60
  text "REV:" at 3638,-655.67 h60
  text ".PCB_Rev" at 3929.5,-655.67 h60
  text "SVN REV:" at 4476,-655.67 h60
  text ".VersionControl_RevNumber" at 4982,-655.67 h60
  text "TID #:" at 2248,-859 h60
  text ".TID" at 2793.5,-859 h60
  text "PLOT NAME =" at -228.5,-1064.34 h60
  text ".plot_File_Name" at 577,-1064.34 h60
  text "GENERATED    :" at 2250,-1064.34 h60
  text ".Print_Date" at 3119.5,-1064.34 h60
  text ".Print_Time" at 3848.5,-1064.34 h60
  text "TEXAS INSTRUMENTS" at 5113,-1064.34 h60
M6 Assembly Bottom:
  lines w10: -292.5,-727.33 6309.5,-727.33 ; -290.5,-930.67 6309.5,-930.67 ; 1115.5,-1140.5 1115.5,-937.67 ; 1737.5,-727.33 1737.5,-524 ; 2577.5,-727.33 2577.5,-524 ; 3844.5,-1134 3844.5,-524 ; 4733.5,-1134 6309,-1134 6309,-524 -292.5,-524 -292.5,-1134 2304.5,-1134 6309.5,-1134 6309.5,-524
  text "COMPONENTS MARKED 'DNP' SHOULD NOT BE POPULATED." at 6102,-318 h60
  text ".VariantName" at 5058,-434 h60
  text "ASSEMBLY VARIANT:" at 6097,-434 h60
  text ".VersionControl_RevNumber" at 1035.5,-656.17 h60
  text "SVN REV:" at 1541.5,-656.17 h60
  text ".PCB_Rev" at 2088,-656.17 h60
  text "REV:" at 2379.5,-656.17 h60
  text ".PRJ_Number" at 3224,-656.17 h60
  text "BOARD #:" at 3769.5,-656.17 h60
  text "PCB VIEWED FROM BOTTOM SIDE" at 6246,-656.17 h60
  text ".TID" at 3224,-859.5 h60
  text "TID #:" at 3769.5,-859.5 h60
  text "TEXAS INSTRUMENTS" at 904.5,-1064.84 h60
  text ".Print_Time" at 2169,-1064.84 h60
  text ".Print_Date" at 2898,-1064.84 h60
  text "GENERATED    :" at 3767.5,-1064.84 h60
  text ".plot_File_Name" at 5440.5,-1064.84 h60
  text "PLOT NAME =" at 6246,-1064.84 h60
M9 Title Sheet:
  drawing of 57 lines, arcs and shapes, not listed
  text "1" at 739.84,8036.5 h70
  text "2" at 3235.5,8036.5 h70
  text "3" at 5724.84,8036.5 h70
  text "4" at 8231.51,8036.5 h70
  text "5" at 10730.5,8036.5 h70
  text "6" at 13235.5,8036.5 h70
  text "A" at -416.5,6893.5 h70
  text "A" at 14383.5,6893.5 h70
  text "B" at -416.5,4513.5 h70
  text "B" at 14383.5,4513.5 h70
  text "C" at -416.5,2138.5 h70
  text "C" at 14383.5,2138.5 h70
  text "PROJECT TITLE:" at 11343.5,277.5 h45
  text ".PRJ_Title" at 11393.5,144.17 h70
  text "DESIGNED FOR:" at 11343.5,-23.5 h45
  text ".PRJ_Customer" at 11393.5,-163.5 h70
  text "D" at -416.5,-231.5 h70
  text "D" at 14383.5,-231.5 h70
  text "FILE NAME:" at 11343.5,-323.5 h45
  text ".PCB_File_Name_No_Path" at 11393.5,-443.5 h70
  text "Texas Instruments (TI) and/or its licensors do not warrant the accuracy or completeness of this specification" at 6374,-605.34 h45
  text "ENGINEER:" at 11343.5,-613.5 h45
  text "LAYOUT BY:" at 12848.5,-613.5 h45
  text "or any information contained therein. TI and/or its licensors do not warrant that this design will meet" at 6329.01,-718 h45
  text ".PRJ_Engineer" at 11393.5,-768.49 h70
  text ".PCB_Layout" at 12899,-768.49 h70
  text "the specifications, will be suitable for your application or fit for any particular purpose, or will operate in" at 6329.01,-830.67 h45
  text ".Layer_Name" at 577,-858.49 h60
  text "ALTIUM DESIGNER VERSION:" at 12848.5,-923.5 h45
  text "an implementation. TI and/or its licensors do not warrant that the design is production worthy. You should" at 6329.01,-943.33 h45
  text "completely validate and test your design implementation to confirm the system functionality for your application." at 6374,-1056 h45
  text ".print_Scale" at 11393.5,-1056.83 h70
  text ".Application_BuildNumber" at 12899,-1056.83 h70
  text "1" at 739.84,-1263.5 h70
  text "2" at 3235.5,-1263.5 h70
  text "3" at 5724.84,-1263.5 h70
  text "4" at 8231.51,-1263.5 h70
  text "5" at 10730.5,-1263.5 h70
  text "6" at 13235.5,-1263.5 h70
M10 Fab Notes:
  drawing of 173 lines, arcs and shapes, not listed
  text "DESIGN INFORMATION" at 12378.02,6201 h60
  text "MIN. TRACK WIDTH:" at 11733.46,6021 h60
  text "8" at 12829.7,6021 h60
  text "MIL" at 12984.46,6021 h60
  text "MIN. CLEARANCE:" at 11733.46,5889 h60
  text "0.2" at 12769.7,5889 h60
  text "mm" at 12984.46,5889 h60
  text "MIN. VIA PAD SIZE:" at 11733.46,5757 h60
  text "24" at 12799.71,5757 h60
  text "MIL" at 12984.46,5757 h60
  text "0.05mm (2MIL)" at 12428.46,5615.29 h60
  text "MINIMUM ANNULAR RING" at 11404.23,5611 h60
  text "EXTERNAL" at 13136.46,5611 h60
  text "PER" at 11604.23,5493 h60
  text "IPC-D-275 CLASS 2 LEVEL C" at 11824.23,5493 h60
  text "MIL, HOLES" at 13312.46,5380.71 h60
  text "+/-" at 12920,5380 h60
  text "+/-" at 13774,5380 h60
  text "REGISTRATION TOLERANCES:" at 11404.23,5375 h60
  text "METAL" at 12604,5375 h60
  text "5" at 13180.2,5375 h60
  text "3" at 14013.2,5375 h60
  text "MIL" at 14129.46,5375 h60
  text "+/-" at 13774,5262 h60
  text "HOLE SIZE TOLERANCE (UNLESS OTHERWISE SPECIFIED):" at 11404.23,5257 h60
  text "3" at 14013.2,5257 h60
  text "MIL" at 14129.46,5257 h60
  text "MATERIAL:" at 11329.46,5047.54 h60
  text "FR-4 High Tg" at 12315.9,4907.21 h60
  text "FR-408" at 11750.46,4898.64 h60
  text "OTHER" at 13238.46,4898.64 h60
  text "X" at 12161,4895 h60
  text "62 MIL (1.6mm) +/-10%" at 12070.56,4735.92 h60
  text "THICKNESS:" at 11404.23,4731.64 h60
  text "X" at 11942.4,4731.64 h60
  text "OTHER" at 13355.46,4731.64 h60
  text "TOLERANCE:" at 11404.23,4573.64 h60
  text "X" at 12243.53,4573.64 h60
  text "ANSI IPC-6012 TYPE 3 CLASS 2" at 12430.48,4573.64 h60
  text "OTHER +/-" at 12430.46,4417.64 h60
  text "BOW & TWIST:" at 11404.23,4260.64 h60
  text "X" at 12243.53,4260.64 h60
  text "ANSI IPC-6012 TYPE 3 CLASS 2" at 12430.48,4260.64 h60
  text "OTHER +/-" at 12430.46,4102.13 h60
  text "DRILLING:" at 11329.46,3963.64 h60
  text "REFERENCE:" at 11404.23,3846.64 h60
  text "X" at 12052.46,3846.64 h60
  text "AS SHOWN" at 12239.46,3846.64 h60
  text "X" at 12953.46,3846.64 h60
  text "NC_DRILL FILES" at 13090.46,3846.64 h60
  text "PTH COPPER THICKNESS:" at 11404.23,3688.64 h60
  text "X" at 12534.46,3688.64 h60
  text "20-30 um" at 12671.46,3688.64 h60
  text "OTHER" at 13388.46,3688.64 h60
  text "BOARD FINISH:" at 11329.46,3529.64 h60
  text "SILKSCREEN:" at 11484.68,3411.64 h60
  text "X" at 12433.46,3411.64 h60
  text "TOP" at 12559.46,3411.64 h60
  text "X" at 12943.46,3411.64 h60
  text "BOTTOM" at 13070.46,3411.64 h60
  text "SILKSCREEN COLOR:" at 11484.68,3244.64 h60
  text "X" at 12432.42,3244.64 h60
  text "WHITE" at 12559.46,3244.64 h60
  text "OTHER" at 13070.46,3244.64 h60
  text "X" at 12560,3090 h60
  text "GREEN" at 12690.46,3085.44 h60
  text "OTHER" at 13308.46,3085.44 h60
  text "SOLDER RESIST COLOR:" at 11484.68,3074.64 h60
  text "X" at 12563.42,2915.44 h60
  text "MATTE" at 12690.46,2915.44 h60
  text "SEMI-GLOSS" at 13308,2914.8 h60
  text "IMMERSION GOLD (ENIG)" at 12390.46,2726.92 h60
  text "ENEPIG" at 13728,2723.64 h60
  text "SURFACE FINISH:" at 11329.46,2722.64 h60
  text "X" at 12203.51,2722.64 h60
  text "IMM. TIN/SILVER OR EQUIV" at 11659,2565.64 h60
  text "OTHER" at 13090.46,2565.64 h60
  text "ARRAY/PANEL:" at 11329.46,2386.64 h60
  text "CUT AND TRIM PER M1 BOARD OUTLINE" at 12390.46,2382.35 h60
  text "N.C. ROUTE" at 12390.46,2230.64 h60
  text "X" at 13069.46,2230.64 h60
  text "V. SCORE" at 13256.46,2230.64 h60
  text "CERTIFICATION:" at 11329.46,2093.64 h60
  text "MATERIALS AND WORKMANSHIP FOR ALL PCBS" at 12054.46,2093.64 h60
  text "TO MEET OR EXCEED THE REQUIREMENTS OF:" at 12054.46,1995.64 h60
  text "X" at 11680.96,1859.13 h60
  text "ANSI IPC-A-600F CLASS ->" at 11819.96,1859.13 h60
  text "X" at 13459.02,1859.13 h60
  text "2" at 13577.96,1859.14 h60
  text "1" at 13262.96,1857.64 h60
  text "3" at 13931.96,1857.64 h60
  text "X" at 12495.02,1699.64 h60
  text "RoHS" at 12631.96,1699.64 h60
  text "OTHER" at 13276.36,1699.64 h60
  text "PER ORDER" at 13673.42,1699.64 h60
  text "ALL BOARDS MUST MEET OR EXCEED UL94-V0 REQUIREMENTS." at 11357,1534 h60
  text "PCB MUST BEAR THE UL94V-0 UL REGISTERED MATERIAL ID NUMBER" at 11357,1414 h60
  text "ADDITIONAL REQUIREMENTS:" at 11329.46,1240.64 h60
  text "MICROSECTION:" at 11404.23,1125.64 h60
  text "YES" at 12309.96,1125.64 h60
  text "X" at 12600,980 h60
  text "REQUIRED" at 13171.46,969.49 h60
  text "BARE BOARD ELEC. TEST:" at 11404.23,966.64 h60
  text "NONE" at 12709.96,966.64 h60
  text "PER ORDER" at 13763.46,966.64 h60
  text ".Layer_Name" at 577,-858.49 h60
M11 Gerber Information:
  lines w10: -292,-930.17 6308,-930.17 ; -292,-726.83 6310,-726.83 ; -292,-523.5 -292,-1133.5 3713,-1133.5 6310,-1133.5 6310,-523.5 -291.5,-523.5 -291.5,-1133.5 1284,-1133.5 ; 2173,-1133.5 2173,-523.5 ; 3440,-726.83 3440,-523.5 ; 4280,-726.83 4280,-523.5 ; 4902,-1140 4902,-937.17
  text "ALL ARTWORK VIEWED FROM TOP SIDE" at -228.5,-655.67 h60
  text "BOARD #:" at 2248,-655.67 h60
  text ".PRJ_Number" at 2793.5,-655.67 h60
  text "REV:" at 3638,-655.67 h60
  text ".PCB_Rev" at 3929.5,-655.67 h60
  text "SVN REV:" at 4476,-655.67 h60
  text ".VersionControl_RevNumber" at 4982,-655.67 h60
  text "LAYER NAME =" at -228.5,-858.49 h60
  text "TID #:" at 2248,-859 h60
  text ".TID" at 2793.5,-859 h60
  text "PLOT NAME =" at -228.5,-1064.34 h60
  text ".plot_File_Name" at 577,-1064.34 h60
  text "GENERATED    :" at 2250,-1064.34 h60
  text ".Print_Date" at 3119.5,-1064.34 h60
  text ".Print_Time" at 3848.5,-1064.34 h60
  text "TEXAS INSTRUMENTS" at 5113,-1064.34 h60
M12 Stackup:
  drawing of 191 lines, arcs and shapes, not listed
  text "Layer" at 9790.09,7800 h60
  text "Name" at 10200,7800 h60
  text "Material" at 11129.74,7800 h60
  text "Thickness" at 11989.51,7800 h60
  text "Constant" at 12639.35,7800 h60
  text "Board Layer Stack" at 13209.21,7800 h60
  text "Top Overlay" at 10200,7680 h60
  text "Top Solder" at 10200,7560 h60
  text "Solder Resist" at 11129.74,7560 h60
  text "0.40mil" at 11989.51,7560 h60
  text "3.5" at 12639.35,7560 h60
  text "1" at 9790.09,7440 h60
  text "Top Layer" at 10200,7440 h60
  text "1.40mil" at 11989.51,7440 h60
  text "Dielectric1" at 10200,7320 h60
  text "FR-4" at 11129.74,7320 h60
  text "59.20mil" at 11989.51,7320 h60
  text "4.8" at 12639.35,7320 h60
  text "2" at 9790.09,7200 h60
  text "Bottom Layer" at 10200,7200 h60
  text "1.40mil" at 11989.51,7200 h60
  text "Bottom Solder" at 10200,7080 h60
  text "Solder Resist" at 11129.74,7080 h60
  text "0.40mil" at 11989.51,7080 h60
  text "3.5" at 12639.35,7080 h60
  text "Bottom Overlay" at 10200,6960 h60
  text ".Layer_Name" at 577,-858.49 h60
M13 Component Bodies Top:
  text ".Layer_Name" at 577,-858.49 h60
M14 Component Bodies Bottom:
  text ".Layer_Name" at 577,-858.49 h60
M15 Courtyards Top:
  text ".Layer_Name" at 577,-858.49 h60
M16 Courtyards Bottom:
  text ".Layer_Name" at 577,-858.49 h60
Drill Drawing:
  circle w10: c3817.44,846.83 r27.56
  lines w10: 3789.88,378.29 3845,378.29 3817.44,323.17 3789.88,378.29 ; 3789.88,447.19 3789.88,460.97 3803.66,474.75 3789.88,488.53 3789.88,502.32 3803.66,502.32 3817.44,488.53 3831.22,502.32 3845,502.32 3845,488.53 3831.22,474.75 3845,460.97 3845,447.19 3831.22,447.19 3817.44,460.97 3803.66,447.19 3789.88,447.19 ; 3789.88,585 3803.66,585 3817.44,571.22 3831.22,585 3845,585 3831.22,598.78 3845,612.56 3831.22,612.56 3817.44,626.34 3803.66,612.56 3789.88,612.56 3803.66,598.78 3789.88,585 ; 3789.88,695.25 3845,695.25 3845,750.37 3789.88,750.37 3789.88,695.25 ; 3789.88,943.3 3817.44,957.08 3845,943.3 3831.22,970.86 3845,998.42 3817.44,984.64 3789.88,998.42 3803.66,970.86 3789.88,943.3
  lines w12: 3739.9,285.96 6966.7,285.96 ; 3739.9,1030.12 6966.7,1030.12 ; 4077.26,161.93 4077.26,1154.14 ; 4408.95,161.93 4408.95,1154.14 ; 5044.81,161.93 5044.81,1154.14 ; 5303.61,161.93 5303.61,1154.14 ; 5678.35,161.93 5678.35,1154.14 ; 6400.9,161.93 6400.9,1154.14 ; 3739.9,161.93 6966.7,161.93 6966.7,1154.14 3739.9,1154.14 3739.9,161.93
  text "Symbol" at 3814.31,1067.33 h72
  text "Quantity" at 4114.47,1067.33 h72
  text "Finished Hole Size" at 4446.16,1067.33 h72
  text "Plated" at 5082.02,1067.33 h72
  text "Hole Type" at 5340.81,1067.33 h72
  text "Drill Layer Pair" at 5715.56,1067.33 h72
  text "Hole Tolerance" at 6438.1,1067.33 h72
  text "19" at 4114.47,943.3 h60
  text "12.00mil (0.305mm)" at 4446.16,943.3 h60
  text "PTH" at 5082.02,943.3 h60
  text "Round" at 5340.81,943.3 h60
  text "Top Layer - Bottom Layer" at 5715.56,943.3 h60
  text "2" at 4114.47,819.27 h60
  text "29.53mil (0.750mm)" at 4446.16,819.27 h60
  text "PTH" at 5082.02,819.27 h60
  text "Round" at 5340.81,819.27 h60
  text "Top Layer - Bottom Layer" at 5715.56,819.27 h60
  text "4" at 4114.47,695.25 h60
  text "33.47mil (0.850mm)" at 4446.16,695.25 h60
  text "PTH" at 5082.02,695.25 h60
  text "Round" at 5340.81,695.25 h60
  text "Top Layer - Bottom Layer" at 5715.56,695.25 h60
  text "8" at 4114.47,571.22 h60
  text "35.43mil (0.900mm)" at 4446.16,571.22 h60
  text "PTH" at 5082.02,571.22 h60
  text "Round" at 5340.81,571.22 h60
  text "Top Layer - Bottom Layer" at 5715.56,571.22 h60
  text "9" at 4114.47,447.19 h60
  text "59.06mil (1.500mm)" at 4446.16,447.19 h60
  text "PTH" at 5082.02,447.19 h60
  text "Round" at 5340.81,447.19 h60
  text "Top Layer - Bottom Layer" at 5715.56,447.19 h60
  text "4" at 4114.47,323.17 h60
  text "63.00mil (1.600mm)" at 4446.16,323.17 h60
  text "PTH" at 5082.02,323.17 h60
  text "Round" at 5340.81,323.17 h60
  text "Top Layer - Bottom Layer" at 5715.56,323.17 h60
  text "46 Total" at 4114.47,199.14 h60
  text ".Layer_Name" at 577,-858.49 h60
M17 Embedded Cavity:
  text ".Layer_Name" at 577,-858.49 h60
M18 Embedded Assembly:
  text ".Layer_Name" at 577,-858.49 h60
M19 Embedded Keepout:
  text ".Layer_Name" at 577,-858.49 h60

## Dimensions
0,-400 to 1000,-400 on M2 Board Dimensions
0,1240 to 3525,0 on M2 Board Dimensions
3525,0 to 0,1240 on M2 Board Dimensions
